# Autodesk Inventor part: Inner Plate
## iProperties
Created: 2002-04
Part Number: Inner Plate
Document SubType Name: Modeling
Control State: 0
Master: False
Checked Out: False
PropertySet Name: Design Tracking Control
Shininess: 77.0
Angle Display Precision: 2
Document Length Units: 11269
Document Angle Units: 11283
Document Time Units: 11279
Document Mass Units: 11290
Document Length Units Precision: 3
Document Angle Units Precision: 2
Compacted: False
PropertySet Name: _Private Model Information
Density: 0.0
Volumn: 0.0
Area: 0.0
PropertySet Name: Model Information
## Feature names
1. Extrusion1
